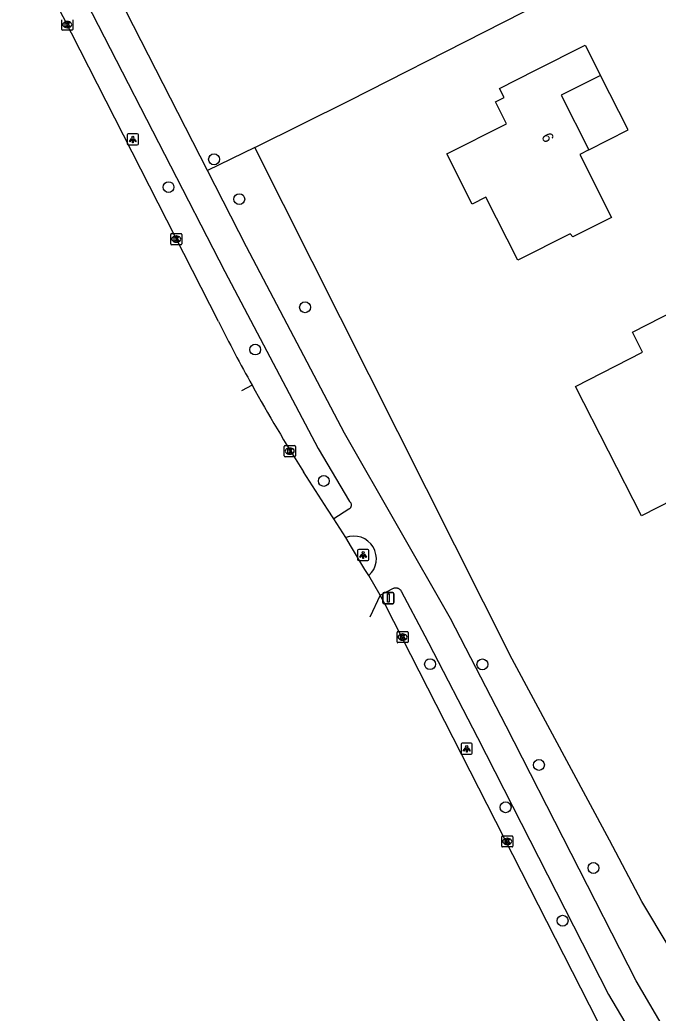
# Model space of a CAD drawing. Extents: x 162722 to 165099, y 384721 to 386283.
# Drawn here: x 163516.5 to 163573.9, y 385021.8 to 385111 of the extents above; entities that cross this region are included whole.
import ezdxf

# ---------------------------------------------------------------- set-up
doc = ezdxf.new("R2010")
doc.units = 0
for name, color, linetype in [('IMGEO_Berm_groen', 7, 'Continuous'), ('IMGEO_Boom', 7, 'Continuous'), ('IMGEO_Fietspad_gesloten', 7, 'Continuous'), ('IMGEO_Gemengd_bos', 7, 'Continuous'), ('IMGEO_Kolk', 7, 'Continuous'), ('IMGEO_Lichtpunt', 7, 'Continuous'), ('IMGEO_Pand', 7, 'Continuous'), ('IMGEO_Pand_nummerreeks', 7, 'Continuous'), ('IMGEO_Pand_overbouw', 7, 'Continuous'), ('IMGEO_Rijbaan_lokaal_gesloten', 7, 'Continuous'), ('IMGEO_Verkeersbordpaal', 7, 'Continuous')]:
    doc.layers.add(name, color=color, linetype=linetype)

msp = doc.modelspace()

# ---------------------------------------------------------------- linework, layer by layer
at = {"layer": 'IMGEO_Berm_groen'}
for points in [[(163537.658, 385099.535), (163533.407, 385097.475)], [(163606.612, 384984.717), (163605.448, 384984.787), (163604.614, 384984.993), (163603.461, 384985.918), (163602.642, 384986.891), (163593.194, 384999.881), (163593.123, 384999.982), (163587.152, 385008.775), (163581.426, 385017.279), (163577.48, 385023.446), (163572.462, 385031.793), (163569.561, 385037.32), (163560.804, 385053.572), (163537.658, 385099.535)]]:
    msp.add_lwpolyline(points, dxfattribs=at)
at = {"layer": 'IMGEO_Boom'}
for centre in [(163534.007, 385098.483), (163529.914, 385095.984), (163536.274, 385094.907), (163542.19, 385085.192), (163537.704, 385081.391), (163543.875, 385069.582), (163553.423, 385053.122), (163558.129, 385053.102), (163563.22, 385044.063), (163560.217, 385040.261), (163568.119, 385034.808), (163565.344, 385030.069)]:
    msp.add_circle(centre, 0.489, dxfattribs=at)
at = {"layer": 'IMGEO_Fietspad_gesloten'}
for points in [[(163533.407, 385097.475), (163520.787, 385122.157)], [(163518.706, 385120.071), (163534.962, 385088.41), (163543.352, 385072.487), (163546.194, 385067.739), (163546.228, 385067.706), (163546.252, 385067.677), (163546.274, 385067.645), (163546.293, 385067.612), (163546.309, 385067.577), (163546.322, 385067.541), (163546.331, 385067.503), (163546.337, 385067.465), (163546.34, 385067.427), (163546.339, 385067.389), (163546.335, 385067.351), (163546.328, 385067.313), (163546.317, 385067.276), (163546.302, 385067.24), (163546.285, 385067.206), (163546.265, 385067.173), (163546.242, 385067.143), (163546.216, 385067.114), (163546.188, 385067.088), (163546.158, 385067.065), (163546.125, 385067.044), (163544.79, 385066.183)], [(163597.022, 384986.15), (163587.589, 385000), (163582.597, 385007.052), (163579.92, 385011.063), (163571.946, 385024.667), (163560.259, 385047.562), (163555.253, 385057.23), (163545.735, 385073.867), (163536.916, 385090.611), (163533.407, 385097.475)], [(163548.928, 385059.309), (163550.136, 385059.946), (163550.173, 385059.96), (163550.22, 385059.973), (163550.268, 385059.982), (163550.317, 385059.987), (163550.366, 385059.987), (163550.415, 385059.983), (163550.463, 385059.975), (163550.511, 385059.962), (163550.557, 385059.945), (163550.601, 385059.924), (163550.643, 385059.899), (163550.683, 385059.871), (163550.721, 385059.839), (163550.755, 385059.804), (163550.786, 385059.766), (163550.813, 385059.725), (163550.837, 385059.682), (163552.943, 385055.659), (163553.294, 385055.053), (163557.697, 385046.522), (163569.478, 385023.427), (163578.544, 385008.07)]]:
    msp.add_lwpolyline(points, dxfattribs=at)
msp.add_arc((163546.575, 385062.6), 2.029, 311.63016, 110.90782, dxfattribs=at)
at = {"layer": 'IMGEO_Gemengd_bos'}
msp.add_lwpolyline([(163537.658, 385099.535), (163546.185, 385103.775), (163570.454, 385116.149), (163559.746, 385137.091)], dxfattribs=at)
at = {"layer": 'IMGEO_Kolk'}
for p, q in [((163520.305, 385110.162), (163520.305, 385111.014)), ((163520.793, 385110.868), (163520.818, 385110.868)), ((163521.306, 385111.014), (163521.306, 385110.162)), ((163521.232, 385110.088), (163520.38, 385110.088)), ((163520.816, 385110.308), (163520.791, 385110.308)), ((163530.108, 385090.889), (163530.108, 385091.741)), ((163530.183, 385091.815), (163531.035, 385091.815)), ((163530.596, 385091.595), (163530.621, 385091.595)), ((163531.109, 385091.741), (163531.109, 385090.889)), ((163531.035, 385090.815), (163530.183, 385090.815)), ((163530.619, 385091.035), (163530.594, 385091.035)), ((163540.314, 385071.838), (163540.314, 385072.69)), ((163540.389, 385072.764), (163541.241, 385072.764)), ((163540.802, 385072.544), (163540.827, 385072.544)), ((163541.315, 385072.69), (163541.315, 385071.838)), ((163541.241, 385071.764), (163540.389, 385071.764)), ((163540.825, 385071.984), (163540.8, 385071.984)), ((163550.457, 385055.128), (163550.457, 385055.98)), ((163550.532, 385056.054), (163551.384, 385056.054)), ((163550.945, 385055.834), (163550.97, 385055.834)), ((163551.458, 385055.98), (163551.458, 385055.128)), ((163551.384, 385055.054), (163550.532, 385055.054)), ((163550.968, 385055.274), (163550.943, 385055.274)), ((163559.943, 385037.695), (163560.795, 385037.695)), ((163559.868, 385036.769), (163559.868, 385037.621)), ((163560.379, 385036.915), (163560.354, 385036.915)), ((163560.356, 385037.475), (163560.381, 385037.475)), ((163560.869, 385037.621), (163560.869, 385036.769)), ((163560.795, 385036.695), (163559.943, 385036.695))]:
    msp.add_line(p, q, dxfattribs=at)
for points in [[(163520.305, 385110.162), (163520.305, 385111.014)], [(163521.306, 385111.014), (163521.306, 385110.162)], [(163521.232, 385110.088), (163520.38, 385110.088)], [(163520.626, 385110.788), (163520.749, 385110.788), (163520.749, 385110.637), (163520.879, 385110.788), (163521.043, 385110.788), (163520.897, 385110.637), (163521.05, 385110.388), (163520.898, 385110.388), (163520.813, 385110.552), (163520.749, 385110.485), (163520.749, 385110.388), (163520.626, 385110.388), (163520.626, 385110.788)], [(163530.108, 385090.889), (163530.108, 385091.741)], [(163530.183, 385091.815), (163531.035, 385091.815)], [(163530.429, 385091.515), (163530.552, 385091.515), (163530.552, 385091.364), (163530.682, 385091.515), (163530.846, 385091.515), (163530.7, 385091.364), (163530.853, 385091.115), (163530.701, 385091.115), (163530.616, 385091.279), (163530.552, 385091.212), (163530.552, 385091.115), (163530.429, 385091.115), (163530.429, 385091.515)], [(163531.109, 385091.741), (163531.109, 385090.889)], [(163531.035, 385090.815), (163530.183, 385090.815)], [(163540.314, 385071.838), (163540.314, 385072.69)], [(163540.389, 385072.764), (163541.241, 385072.764)], [(163541.315, 385072.69), (163541.315, 385071.838)], [(163541.241, 385071.764), (163540.389, 385071.764)], [(163540.635, 385072.464), (163540.758, 385072.464), (163540.758, 385072.313), (163540.888, 385072.464), (163541.052, 385072.464), (163540.906, 385072.313), (163541.059, 385072.064), (163540.907, 385072.064), (163540.822, 385072.228), (163540.758, 385072.161), (163540.758, 385072.064), (163540.635, 385072.064), (163540.635, 385072.464)], [(163550.457, 385055.128), (163550.457, 385055.98)], [(163550.532, 385056.054), (163551.384, 385056.054)], [(163550.778, 385055.754), (163550.901, 385055.754), (163550.901, 385055.603), (163551.031, 385055.754), (163551.195, 385055.754), (163551.049, 385055.603), (163551.202, 385055.354), (163551.05, 385055.354), (163550.965, 385055.518), (163550.901, 385055.451), (163550.901, 385055.354), (163550.778, 385055.354), (163550.778, 385055.754)], [(163551.458, 385055.98), (163551.458, 385055.128)], [(163551.384, 385055.054), (163550.532, 385055.054)], [(163559.943, 385037.695), (163560.795, 385037.695)], [(163559.868, 385036.769), (163559.868, 385037.621)], [(163560.189, 385037.395), (163560.312, 385037.395), (163560.312, 385037.244), (163560.442, 385037.395), (163560.606, 385037.395), (163560.46, 385037.244), (163560.613, 385036.995), (163560.461, 385036.995), (163560.376, 385037.159), (163560.312, 385037.092), (163560.312, 385036.995), (163560.189, 385036.995), (163560.189, 385037.395)], [(163560.869, 385037.621), (163560.869, 385036.769)], [(163560.795, 385036.695), (163559.943, 385036.695)]]:
    msp.add_lwpolyline(points, dxfattribs=at)
for centre, start, end in [((163520.382, 385110.164), 181.55205, 268.44795), ((163520.382, 385110.164), 181.55205, 268.44795), ((163521.23, 385110.164), 271.55205, 358.44795), ((163521.23, 385110.164), 271.55205, 358.44795), ((163530.185, 385091.739), 91.55205, 178.44795), ((163530.185, 385091.739), 91.55205, 178.44795), ((163531.033, 385091.739), 1.55205, 88.44795), ((163531.033, 385091.739), 1.55205, 88.44795), ((163530.185, 385090.891), 181.55205, 268.44795), ((163530.185, 385090.891), 181.55205, 268.44795), ((163531.033, 385090.891), 271.55205, 358.44795), ((163531.033, 385090.891), 271.55205, 358.44795), ((163540.391, 385072.688), 91.55205, 178.44795), ((163540.391, 385072.688), 91.55205, 178.44795), ((163541.239, 385072.688), 1.55205, 88.44795), ((163541.239, 385072.688), 1.55205, 88.44795), ((163540.391, 385071.84), 181.55205, 268.44795), ((163540.391, 385071.84), 181.55205, 268.44795), ((163541.239, 385071.84), 271.55205, 358.44795), ((163541.239, 385071.84), 271.55205, 358.44795), ((163550.534, 385055.978), 91.55205, 178.44795), ((163550.534, 385055.978), 91.55205, 178.44795), ((163551.382, 385055.978), 1.55205, 88.44795), ((163551.382, 385055.978), 1.55205, 88.44795), ((163550.534, 385055.13), 181.55205, 268.44795), ((163550.534, 385055.13), 181.55205, 268.44795), ((163551.382, 385055.13), 271.55205, 358.44795), ((163551.382, 385055.13), 271.55205, 358.44795), ((163559.945, 385037.619), 91.55205, 178.44795), ((163559.945, 385037.619), 91.55205, 178.44795), ((163560.793, 385037.619), 1.55205, 88.44795), ((163560.793, 385037.619), 1.55205, 88.44795), ((163559.945, 385036.771), 181.55205, 268.44795), ((163559.945, 385036.771), 181.55205, 268.44795), ((163560.793, 385036.771), 271.55205, 358.44795), ((163560.793, 385036.771), 271.55205, 358.44795)]:
    msp.add_arc(centre, 0.0765, start, end, dxfattribs=at)
for centre, major_axis, ratio, start_param, end_param in [((163520.792, 385110.588), (-0.387, 0.002), 0.722429, 4.712389, 7.853982), ((163520.817, 385110.588), (-0.39, 0.002), 0.717154, 1.570796, 4.712389), ((163530.595, 385091.315), (-0.387, 0.002), 0.722429, 4.712389, 7.853982), ((163530.62, 385091.315), (-0.39, 0.002), 0.717154, 1.570796, 4.712389), ((163540.801, 385072.264), (-0.387, 0.002), 0.722429, 4.712389, 7.853982), ((163540.826, 385072.264), (-0.39, 0.002), 0.717154, 1.570796, 4.712389), ((163550.944, 385055.554), (-0.387, 0.002), 0.722429, 4.712389, 7.853982), ((163550.969, 385055.554), (-0.39, 0.002), 0.717154, 1.570796, 4.712389), ((163560.355, 385037.195), (-0.387, 0.002), 0.722429, 4.712389, 7.853982), ((163560.38, 385037.195), (-0.39, 0.002), 0.717154, 1.570796, 4.712389)]:
    msp.add_ellipse(centre, major_axis=major_axis, ratio=ratio, start_param=start_param, end_param=end_param, dxfattribs=at)
at = {"layer": 'IMGEO_Lichtpunt'}
for p, q in [((163526.203, 385100.676), (163526.203, 385099.869)), ((163526.203, 385100.676), (163526.203, 385099.869)), ((163527.105, 385100.771), (163526.297, 385100.771)), ((163527.105, 385100.771), (163526.297, 385100.771)), ((163527.199, 385099.869), (163527.199, 385100.676)), ((163527.199, 385099.869), (163527.199, 385100.676)), ((163526.297, 385099.775), (163527.105, 385099.775)), ((163526.297, 385099.775), (163527.105, 385099.775)), ((163546.916, 385063.333), (163546.916, 385062.526)), ((163546.916, 385063.333), (163546.916, 385062.526)), ((163547.818, 385063.428), (163547.01, 385063.428)), ((163547.818, 385063.428), (163547.01, 385063.428)), ((163547.912, 385062.526), (163547.912, 385063.333)), ((163547.912, 385062.526), (163547.912, 385063.333)), ((163547.01, 385062.432), (163547.818, 385062.432)), ((163547.01, 385062.432), (163547.818, 385062.432)), ((163556.229, 385045.929), (163556.229, 385045.122)), ((163556.229, 385045.929), (163556.229, 385045.122)), ((163557.131, 385046.024), (163556.323, 385046.024)), ((163557.131, 385046.024), (163556.323, 385046.024)), ((163557.225, 385045.122), (163557.225, 385045.929)), ((163557.225, 385045.122), (163557.225, 385045.929)), ((163556.323, 385045.028), (163557.131, 385045.028)), ((163556.323, 385045.028), (163557.131, 385045.028))]:
    msp.add_line(p, q, dxfattribs=at)
for points in [[(163526.577, 385100.34), (163526.616, 385100.312), (163526.428, 385100.05), (163526.39, 385100.077), (163526.577, 385100.34)], [(163526.679, 385100.292), (163526.726, 385100.292), (163526.726, 385099.97), (163526.679, 385099.97), (163526.679, 385100.292)], [(163526.789, 385100.312), (163526.827, 385100.339), (163527.014, 385100.077), (163526.975, 385100.049), (163526.789, 385100.312)], [(163547.29, 385062.997), (163547.329, 385062.969), (163547.141, 385062.707), (163547.103, 385062.734), (163547.29, 385062.997)], [(163547.392, 385062.949), (163547.439, 385062.949), (163547.439, 385062.627), (163547.392, 385062.627), (163547.392, 385062.949)], [(163547.502, 385062.969), (163547.54, 385062.996), (163547.727, 385062.734), (163547.688, 385062.706), (163547.502, 385062.969)], [(163556.603, 385045.593), (163556.642, 385045.565), (163556.454, 385045.303), (163556.416, 385045.33), (163556.603, 385045.593)], [(163556.705, 385045.545), (163556.752, 385045.545), (163556.752, 385045.223), (163556.705, 385045.223), (163556.705, 385045.545)], [(163556.815, 385045.565), (163556.853, 385045.592), (163557.04, 385045.33), (163557.001, 385045.302), (163556.815, 385045.565)]]:
    msp.add_lwpolyline(points, dxfattribs=at)
for centre in [(163526.702, 385100.474), (163547.415, 385063.131), (163556.728, 385045.727)]:
    msp.add_circle(centre, 0.0994, dxfattribs=at)
for centre, start, end in [((163526.297, 385100.676), 90, 180), ((163526.297, 385100.676), 90, 180), ((163527.105, 385100.676), 0, 90), ((163527.105, 385100.676), 0, 90), ((163526.297, 385099.869), 180, 270), ((163526.297, 385099.869), 180, 270), ((163527.105, 385099.869), 270, 0), ((163527.105, 385099.869), 270, 360), ((163547.01, 385063.333), 90, 180), ((163547.01, 385063.333), 90, 180), ((163547.818, 385063.333), 0, 90), ((163547.818, 385063.333), 0, 90), ((163547.01, 385062.526), 180, 270), ((163547.01, 385062.526), 180, 270), ((163547.818, 385062.526), 270, 0), ((163547.818, 385062.526), 270, 360), ((163556.323, 385045.929), 90, 180), ((163556.323, 385045.929), 90, 180), ((163557.131, 385045.929), 0, 90), ((163557.131, 385045.929), 0, 90), ((163556.323, 385045.122), 180, 270), ((163556.323, 385045.122), 180, 270), ((163557.131, 385045.122), 270, 0), ((163557.131, 385045.122), 270, 360)]:
    msp.add_arc(centre, 0.0946, start, end, dxfattribs=at)
at = {"layer": 'IMGEO_Pand'}
for points in [[(163568.75, 385106.028), (163565.216, 385104.244), (163567.695, 385099.335), (163566.883, 385098.925), (163569.744, 385093.261), (163566.266, 385091.505), (163566.02, 385091.797), (163561.31, 385089.419), (163558.456, 385095.072), (163557.213, 385094.444), (163554.931, 385098.962), (163560.311, 385101.679), (163559.31, 385103.661), (163560.08, 385104.05), (163559.676, 385104.851), (163562.916, 385106.487), (163567.379, 385108.741), (163568.75, 385106.028)], [(163581.874, 385080.405), (163578.081, 385078.468), (163579.259, 385076.162), (163580.054, 385076.568), (163582.578, 385071.627), (163578.126, 385069.353), (163572.432, 385066.444), (163566.491, 385078.074), (163572.535, 385081.162), (163571.621, 385082.952), (163574.268, 385084.304), (163578.72, 385086.578), (163581.874, 385080.405)]]:
    msp.add_lwpolyline(points, dxfattribs=at)
at = {"layer": 'IMGEO_Pand_overbouw'}
msp.add_lwpolyline([(163568.75, 385106.028), (163565.216, 385104.244), (163567.695, 385099.335), (163571.23, 385101.12)], close=True, dxfattribs=at)
at = {"layer": 'IMGEO_Rijbaan_lokaal_gesloten'}
for points in [[(163534.395, 385083.912), (163516.545, 385118.94)], [(163537.421, 385078.191), (163536.486, 385077.671)], [(163544.79, 385066.183), (163544.201, 385067.057), (163542.048, 385070.407)], [(163545.851, 385064.495), (163544.79, 385066.183)], [(163547.923, 385061.083), (163547.569, 385061.641), (163546.364, 385063.642), (163545.851, 385064.495)], [(163548.928, 385059.309), (163547.923, 385061.083)], [(163548.928, 385059.309), (163548.01, 385057.354)], [(163589.269, 384982.185), (163585.242, 384988.904), (163580.059, 384998.396), (163579.239, 385000), (163549.378, 385058.477), (163548.928, 385059.309)]]:
    msp.add_lwpolyline(points, dxfattribs=at)
for centre, radius, start, end in [((163672.962, 385153.543), 155.079, 206.67997, 209.07131), ((163671.963, 385152.899), 153.893, 209.04234, 212.41423)]:
    msp.add_arc(centre, radius, start, end, dxfattribs=at)
at = {"layer": 'IMGEO_Verkeersbordpaal'}
for p, q in [((163549.187, 385058.656), (163549.187, 385059.456)), ((163549.187, 385059.456), (163549.187, 385058.656)), ((163549.287, 385059.556), (163550.077, 385059.556)), ((163550.077, 385059.556), (163549.287, 385059.556)), ((163550.177, 385059.456), (163550.177, 385058.656)), ((163550.177, 385058.656), (163550.177, 385059.456)), ((163550.077, 385058.556), (163549.287, 385058.556)), ((163549.287, 385058.556), (163550.077, 385058.556))]:
    msp.add_line(p, q, dxfattribs=at)
msp.add_lwpolyline([(163549.607, 385059.431), (163549.757, 385059.431), (163549.757, 385058.681), (163549.607, 385058.681), (163549.607, 385059.431)], dxfattribs=at)
for centre, start, end in [((163549.287, 385059.456), 90, 180), ((163549.287, 385059.456), 90, 180), ((163550.077, 385059.456), 0, 90), ((163550.077, 385059.456), 360, 90), ((163549.287, 385058.656), 180, 270), ((163549.287, 385058.656), 180, 270), ((163550.077, 385058.656), 270, 0), ((163550.077, 385058.656), 270, 0)]:
    msp.add_arc(centre, 0.1, start, end, dxfattribs=at)

# ---------------------------------------------------------------- texts
at = {"layer": 'IMGEO_Pand_nummerreeks'}
msp.add_text('6', height=1, rotation=296.79336, dxfattribs=at).set_placement((163563.404, 385100.556))

doc.saveas('drawing.dxf')
